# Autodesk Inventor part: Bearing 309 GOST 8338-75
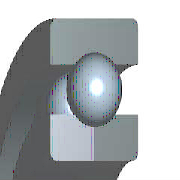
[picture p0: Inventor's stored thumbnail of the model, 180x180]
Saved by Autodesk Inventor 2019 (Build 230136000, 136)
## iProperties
Created: 2018-01
Part Number: Bearing 309 GOST 8338-75
Material: Steel, Mild
Description: Single row radial ball bearings
Document SubType Name: Modeling
Standard: GOST 8338-75
Designer: m.vorobev
Standards Organization: GOST
Language: en-US
Size Designation: 309
Categories: <MemberInstance><Categories><Category DisplayName="Shaft Parts" InternalName="7f7aeb1f-a693-4053-b835-cee3144e0d98" Mnemonic="SHFT"><Category DisplayName="Beari
Density: 7.85 g/cm^3
Appearance: Semi-Polished
IsCustomPart: 0
Author: m.vorobev
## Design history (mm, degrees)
sketch "Sketch" dims "d3" = 14.3 (= 0.26 x BD - 0.26 x WD)
  geometry: L1 (12.5, 29.1)-(12.5, 43.4); L2 (7.187, 41.035)-(0, 41.035); L3 (7.187, 31.465)-(0, 31.465); L4 (0, 22.5)-(25, 22.5); L5 (0, 50)-(25, 50); L6 (25, 22.5)-(25, 31.465); L7 (25, 41.035)-(25, 50); L8 (17.813, 41.035)-(25, 41.035); L9 (17.813, 31.465)-(25, 31.465); L10 (12.5, 36.25)-(19.65, 36.25); L11 (12.5, 36.25)-(5.35, 36.25); L12 (-1.4, 0)-(8.4, 0) reference; L13 (0, -0.5)-(0, 4.75) reference
  constraints: 22 end point, 4 point on line, 3 collinear, 3 parallel, 2 perpendicular, 2 symmetric about line, 1 midpoint, 10 other
  dimensions: "d7" = 45 diameter of L4 L12 (= WD); "d8" = 100 diameter of L5 L12 (= BD); "d10" = 25 distance between parallel lines of L13 L6 (= KB); "d11" = 72.5 diameter of L10.start L12 (= 0.5 x WD + 0.5 x BD); "d13" = 62.93 diameter of L3 L12 (= 0.326 x BD + 0.674 x WD); "d15" = 82.07 diameter of L2 L12 (= 0.674 x BD + 0.326 x WD)
revolve "Body" stored, may be unused: angle "d9" = 90 deg
revolve "Ball" stored, may be unused: angle "d12" = 90 deg
pattern_circular "Balls" dims angle "d2" = 360 deg
body "Solid1"
fillet "Fillet1" dims "d0" = 3 (= KRS)
other parameters: "WD" = 45 [user parameter; used in 7 equation terms], "BD" = 100 [user parameter; used in 7 equation terms], "KB" = 25 [user parameter; used in 1 equation term], "KRS" = 3 [user parameter; used in 1 equation term], "d4" = 0, "d5" = 0, "d6" = 0, "d16" = 0, "d17" = 0, "BBA" = 0 [user parameter], "BC0" = 3e+07 [user parameter], "BC" = 5.27e+07 [user parameter], "WR" = 22.5 (= 0.5 x WD) [user parameter]
